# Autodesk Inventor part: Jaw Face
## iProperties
Shininess: 77.0
Length Units: 11269
Angle Units: 11279
Time Units: 11290
Mass Units: 11283
Length Display Precision: 3
Angle Display Precision: 2
Compacted: True
Created: 2002-02
Part Number: Jaw Face
Document SubType Name: Modeling
Designer: ***
Density: 0.0
Volumn: 0.0
Area: 0.0
PropertySet Name: Model Information
Control State: 0
Master: False
Checked Out: False
Author: ***
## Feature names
1. Extrusion1
